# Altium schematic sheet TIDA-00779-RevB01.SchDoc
size 431 x 279 mm; Date: Not shown in title block; ApprovedBy: Not shown in title block; CheckedBy: Not shown in title block; Author: Not shown in title block; CompanyName: Not shown in title block; Engineer: Not shown in title block; Organization: Not shown in title block; Address1: Not shown in title block; Address2: Not shown in title block; Address3: Not shown in title block; Address4: Not shown in title block; DocumentNumber: 1; Revision: Use project parameter SCH_Rev; SheetNumber: 2; SheetTotal: 3; PageSetup: Record=PageOptions¦CenterHorizontal=True¦CenterVertical=True¦PrintScale=0.62¦XCorrection=1.00¦YCorrection=1.00¦PrintKind=0¦BorderSize=5000000¦LeftOffset=0¦BottomOffset=0¦Orientation=2¦PaperLength=1000¦PaperWidth=1000¦Scale=100¦PaperSource=15¦PrintQuality=600¦MediaType=1¦DitherType=10¦PaperKind=Letter¦PrintScaleMode=1
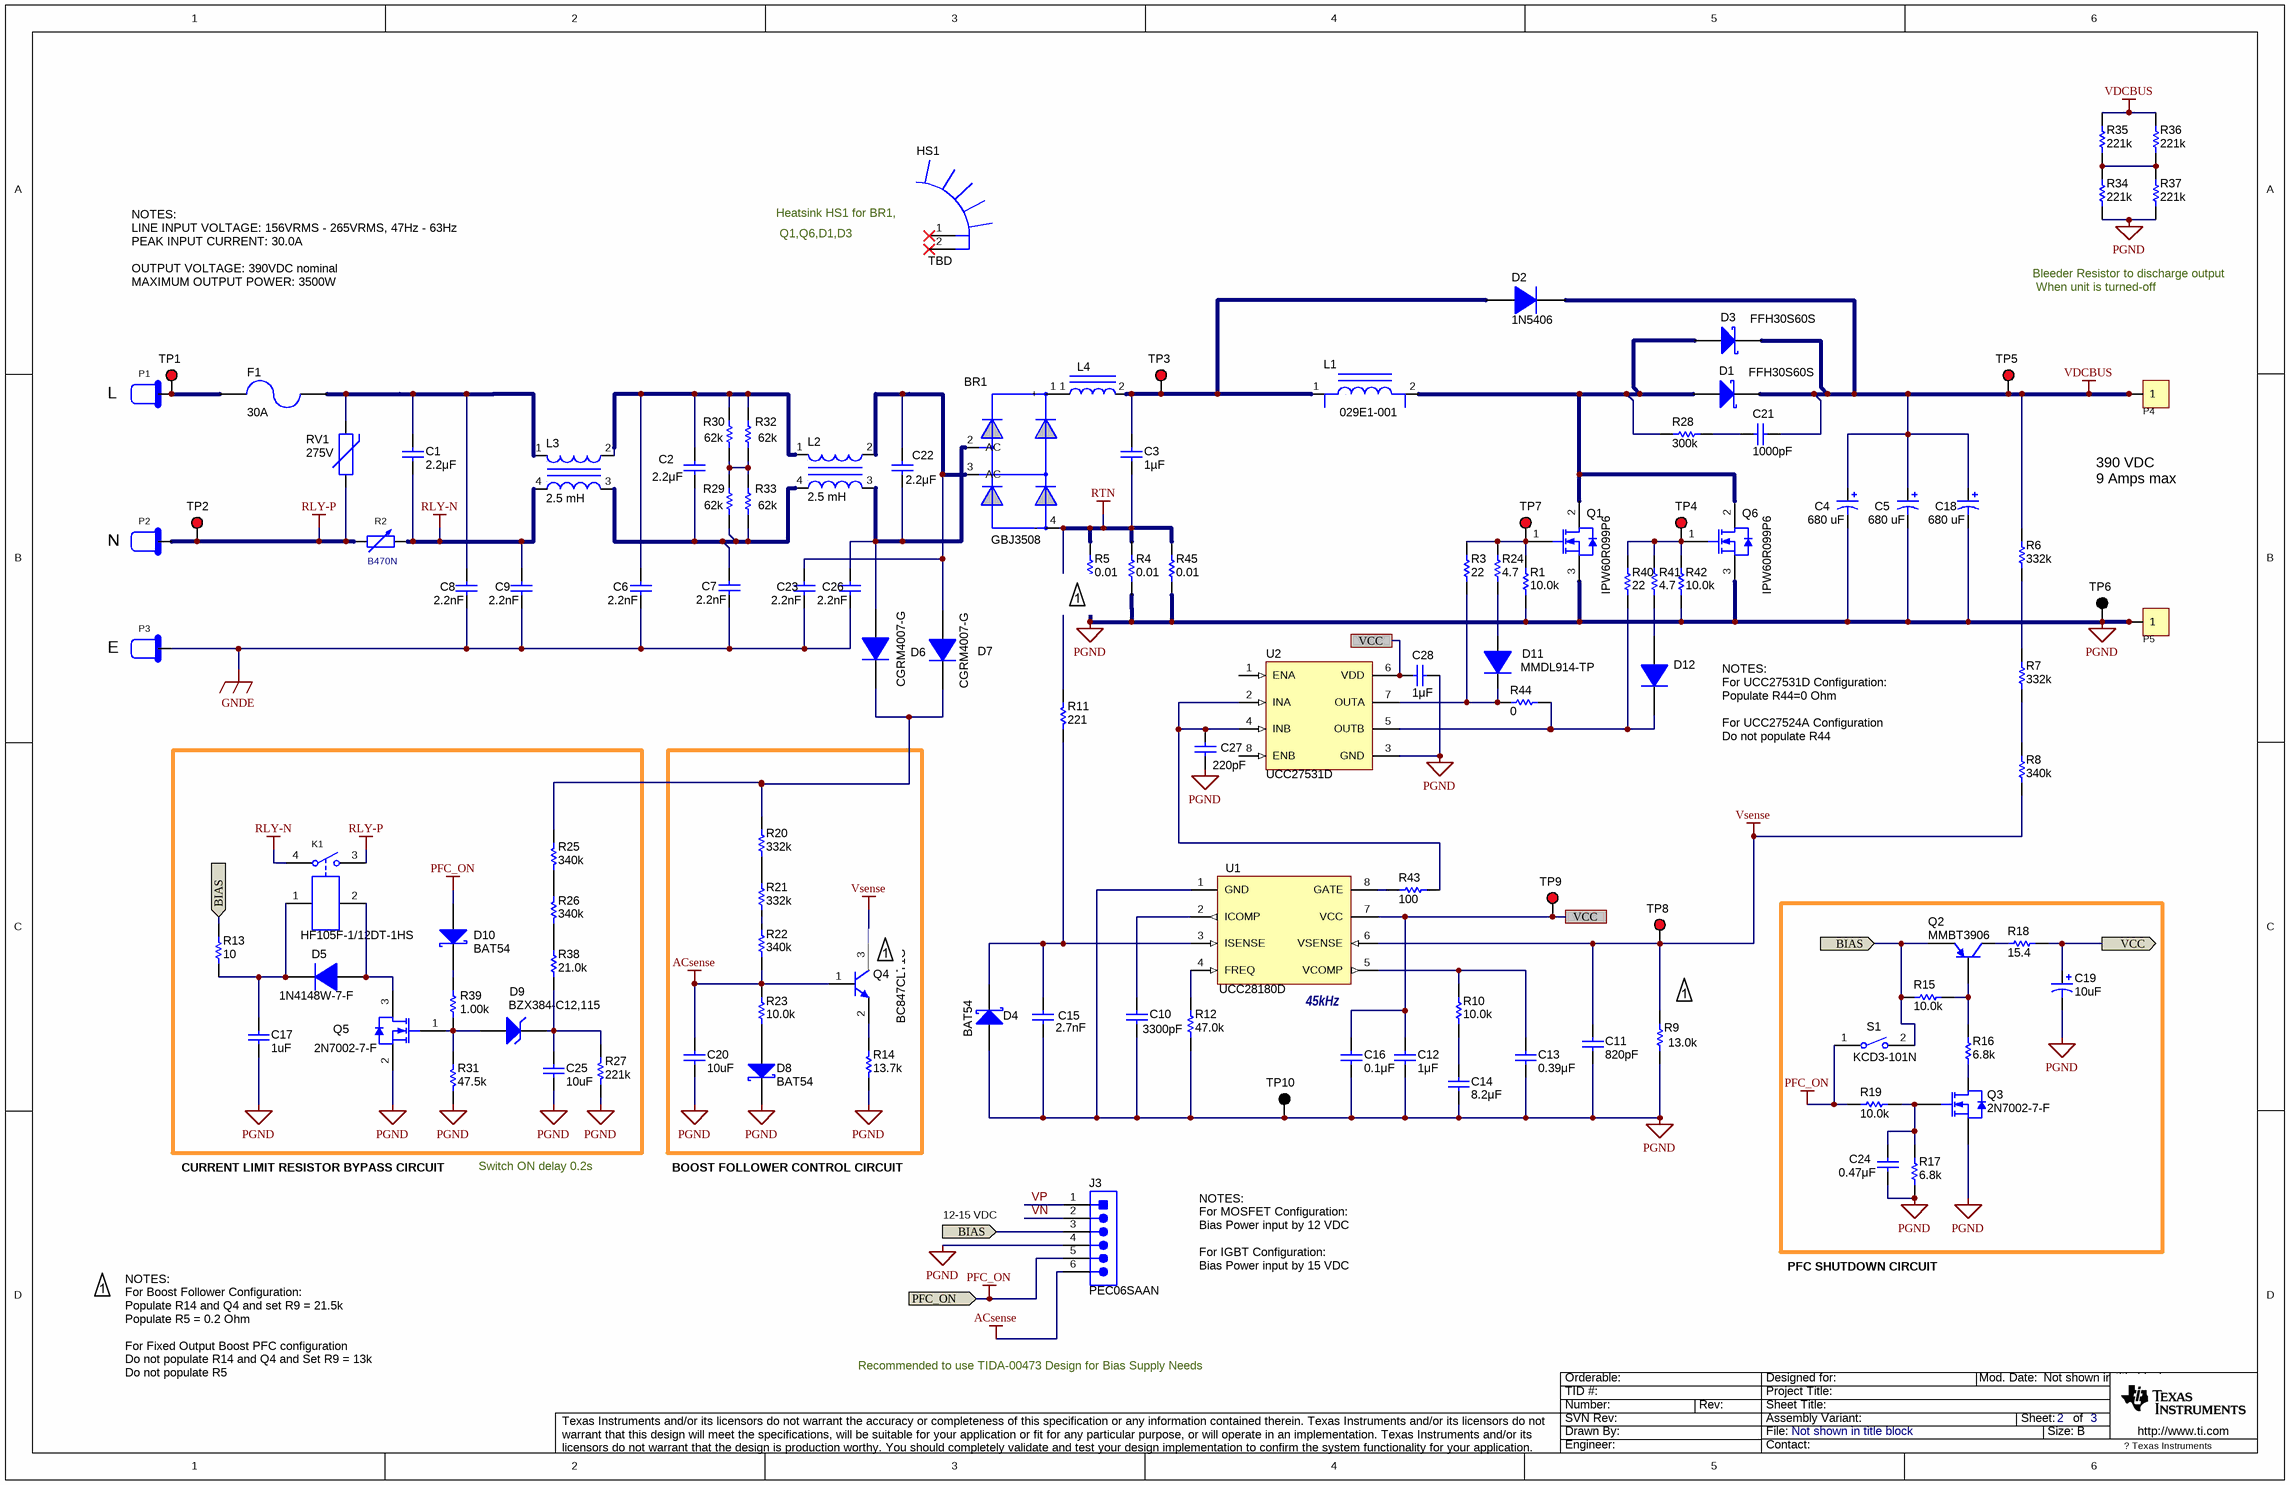
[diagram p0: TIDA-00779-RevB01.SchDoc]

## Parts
BR1  GBJ3508  [BRIDGE-GBJ1510-BV]
C1  ValueDisplayed: 2.2μF  [B32923_29.5mm]  (hidden comment: B32923C3225K)
C2  ValueDisplayed: 2.2μF  [B32923_29.5mm]  (hidden comment: B32923C3225K)
C3  ValueDisplayed: 1µF  [B32923_20.5mm]  (hidden comment: B32923C3105K)
C4  value 680 uF  [E/P10/D36/E2]  (hidden comment: LGG2W681MELC50)
C5  value 680 uF  [E/P10/D36/E2]  (hidden comment: LGG2W681MELC50)
C6  2.2nF  [C/10/12/5]
C7  2.2nF  [C/10/12/5]
C8  2.2nF  [C/10/12/5]
C9  2.2nF  [C/10/12/5]
C10  ValueDisplayed: 3300pF  [0603]  (hidden comment: GRM188R71H472KA01D)
C11  ValueDisplayed: 820pF  [0603]  (hidden comment: C0603C821K5RACTU)
C12  ValueDisplayed: 1μF  [0603_095]  (hidden comment: C0603C105K3RACTU)
C13  ValueDisplayed: 0.39μF  [0603]  (hidden comment: C0603C394K4RACTU)
C14  ValueDisplayed: 8.2μF  [0603]  (hidden comment: 0603ZD475KAT2A)
C15  ValueDisplayed: 2.7nF  [0603]  (hidden comment: 06031C272JAT2A)
C16  ValueDisplayed: 0.1μF  [0603]  (hidden comment: 0603YC104JAT2A)
C17  ValueDisplayed: 1uF  [0603]  (hidden comment: C1608X7R1E105K080AB)
C18  value 680 uF  [E/P10/D36/E2]  (hidden comment: LGG2W681MELC50)
C19  ValueDisplayed: 10uF  [PW_500x700]  (hidden comment: UPW1V100MDD6)
C20  ValueDisplayed: 10uF  [0805_HV]  (hidden comment: C2012X5R1E106K125AB)
C21  ValueDisplayed: 1000pF  [1206]  (hidden comment: 1206AC102KAT1A)
C22  ValueDisplayed: 2.2μF  [B32923_29.5mm]  (hidden comment: B32923C3225K)
C23  2.2nF  [C/10/12/5]
C24  ValueDisplayed: 0.47μF  [0603]  (hidden comment: C0603C474K4RACTU)
C25  ValueDisplayed: 10uF  [1206]  (hidden comment: UMK316BBJ106ML-T)
C26  2.2nF  [C/10/12/5]
C27  ValueDisplayed: 220pF  [0603]  (hidden comment: C1608X7R1H221K)
C28  ValueDisplayed: 1μF  [0603]  (hidden comment: UMK107AB7105KA-T)
D1  FFH30S60S  [TO247BV-D]
D2  1N5406  [DO-201AD]
D3  FFH30S60S  [TO247BV-D]
D4  Alternate PartNumber: BAT54  [sod-323]  (hidden comment: BAT54HT1G)
D5  1N4148W-7-F  [SOD-123]
D6  CGRM4007-G  [MINI-SMA]
D7  CGRM4007-G  [MINI-SMA]
D8  Alternate PartNumber: BAT54  [sod-323]  (hidden comment: BAT54HT1G)
D9  BZX384-C12,115  [sod-323]
D10  Alternate PartNumber: BAT54  [sod-323]  (hidden comment: BAT54HT1G)
D11  MMDL914-TP  [sod-323]
D12  MMDL914-TP  [sod-323]  (value not drawn)
F1  30A  [TBD]
HS1  TBD  [HS_ASS_0595]
J3  PEC06SAAN  [HDR1X6]
K1  HF105F-1/12DT-1HS  [RY-SLA-S112DM1]
L1  029E1-001  [L4p-55*50P40*45]
L2  2.5 mH  [L4p-56*42P42*38-LT38-4P]
L3  2.5 mH  [L4p-56*42P42*38-LT38-4P]
L4  (no value)
P1  L  [P-CONNECT]
P2  N  [P-CONNECT]
P3  E  [P-CONNECT]
P4  TH  [PCB-7(M4)]  (value not drawn)
P5  TH  [PCB-7(M4)]  (value not drawn)
Q1  IPW60R099P6  [TO-247BV2]
Q2  MMBT3906  [SOT-23]
Q3  2N7002-7-F  [SOT-23]
Q4  BC847CLT1G  [SOT-23]
Q5  2N7002-7-F  [SOT-23]
Q6  IPW60R099P6  [TO-247BV2]
R1  ValueDisplayed: 10.0k  [0603]  (hidden comment: CRCW060310K0FKEA)
R2  B470N  [PTC-18*13P10]
R3  ValueDisplayed: 22  [1206]  (hidden comment: CRCW120622R0JNEA)
R4  ValueDisplayed: 0.01  [R/P10/5W]
R5  ValueDisplayed: 0.01  [R/P10/5W]
R6  ValueDisplayed: 332k  [1206]  (hidden comment: CRCW1206332KFKEA)
R7  ValueDisplayed: 332k  [1206]  (hidden comment: CRCW1206332KFKEA)
R8  ValueDisplayed: 340k  [1206]  (hidden comment: CRCW1206340KFKEA)
R9  ValueDisplayed: 13.0k  [0603]  (hidden comment: CRCW060313K0FKEA)
R10  ValueDisplayed: 10.0k  [0603]  (hidden comment: CRCW060310K0FKEA)
R11  value 221  [0603M]  (hidden comment: CRCW0603221RFKEA)
R12  ValueDisplayed: 47.0k  [0603]  (hidden comment: RT0603DRE0747KL)
R13  ValueDisplayed: 10  [1206]  (hidden comment: CRCW1206100RFKEA)
R14  ValueDisplayed: 13.7k  [0603]  (hidden comment: CRCW060313K7FKEA)
R15  value 10.0k  [0603]  (hidden comment: CRCW060310K0FKEA)
R16  ValueDisplayed: 6.8k  [0603]  (hidden comment: CRCW06036K80JNEA)
R17  ValueDisplayed: 6.8k  [0603]  (hidden comment: CRCW06036K80JNEA)
R18  ValueDisplayed: 15.4  [0603]  (hidden comment: CRCW060315R4FKEA)
R19  value 10.0k  [0603]  (hidden comment: CRCW060310K0FKEA)
R20  ValueDisplayed: 332k  [1206]  (hidden comment: CRCW1206332KFKEA)
R21  ValueDisplayed: 332k  [1206]  (hidden comment: CRCW1206332KFKEA)
R22  ValueDisplayed: 340k  [1206]  (hidden comment: CRCW1206340KFKEA)
R23  ValueDisplayed: 10.0k  [0603]  (hidden comment: CRCW060310K0FKEA)
R24  ValueDisplayed: 4.7  [1206]  (hidden comment: CRCW12064R70JNEA)
R25  ValueDisplayed: 340k  [1206]  (hidden comment: CRCW1206340KFKEA)
R26  ValueDisplayed: 340k  [1206]  (hidden comment: CRCW1206340KFKEA)
R27  ValueDisplayed: 221k  [0603]  (hidden comment: CRCW0603221KFKEA)
R28  ValueDisplayed: 300k  [R5/D4.4V]  (hidden comment: CRM2512-FX-43R2ELF)
R29  ValueDisplayed: 62k  [2512]  (hidden comment: CRCW251262K0JNEG)
R30  ValueDisplayed: 62k  [2512]  (hidden comment: CRCW251262K0JNEG)
R31  ValueDisplayed: 47.5k  [0603]  (hidden comment: CRCW060347K5FKEA)
R32  ValueDisplayed: 62k  [2512]  (hidden comment: CRCW251262K0JNEG)
R33  ValueDisplayed: 62k  [2512]  (hidden comment: CRCW251262K0JNEG)
R34  ValueDisplayed: 221k  [1206]  (hidden comment: CRCW1206221KFKEA)
R35  ValueDisplayed: 221k  [1206]  (hidden comment: CRCW1206221KFKEA)
R36  ValueDisplayed: 221k  [1206]  (hidden comment: CRCW1206221KFKEA)
R37  ValueDisplayed: 221k  [1206]  (hidden comment: CRCW1206221KFKEA)
R38  ValueDisplayed: 21.0k  [1206]  (hidden comment: CRCW120621K0FKEA)
R39  ValueDisplayed: 1.00k  [0603]  (hidden comment: CRCW06031K00FKEA)
R40  ValueDisplayed: 22  [1206]  (hidden comment: CRCW120622R0JNEA)
R41  ValueDisplayed: 4.7  [1206]  (hidden comment: CRCW12064R70JNEA)
R42  ValueDisplayed: 10.0k  [0603]  (hidden comment: CRCW060310K0FKEA)
R43  ValueDisplayed: 100  [0603]  (hidden comment: RT0603DRE07100RL)
R44  ValueDisplayed: 0  [1206]  (hidden comment: RC1206JR-070RL)
R45  ValueDisplayed: 0.01  [R/P10/5W]
RV1  value 275V  [VAR_S10K275E2]  (hidden comment: S10K275E2)
S1  KCD3-101N
TP1  5000  [Keystone5000]  (value not drawn)
TP2  5000  [Keystone5000]  (value not drawn)
TP3  5000  [Keystone5000]  (value not drawn)
TP4  5000  [Keystone5000]  (value not drawn)
TP5  5000  [Keystone5000]  (value not drawn)
TP6  5001  [Keystone5001]  (value not drawn)
TP7  5000  [Keystone5000]  (value not drawn)
TP8  5000  [Keystone5000]  (value not drawn)
TP9  5000  [Keystone5000]  (value not drawn)
TP10  5001  [Keystone5001]  (value not drawn)
U1  UCC28180D  [D0008A_N]
U2  UCC27531D  [D0008A_N]

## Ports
BIAS, PFC_ON (in), VCC

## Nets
ACsense: C20.1 J3.6 Q4.1(B) R22.1 R23.1
GNDE: C6.2 C7.2 C8.2 C9.2 C23.2 C26.2 P3.1
PFC_ON: D10.2(A) J3.5 R19.1 S1.1 ; port PFC_ON
PGND: C4.2(-) C5.2(-) C10.2 C11.2 C12.2 C13.2 C14.2 C15.2 C16.2 C17.2 C18.2(-) C19.2(-) C20.2 C24.2 C25.2 C27.2 C28.1 D4.2(A) D8.1(K) J3.4 P5.1 P5.2 P5.3 P5.4 Q1.3(S) Q3.2(S) Q5.2(S) Q6.3(S) R1.2 R4.1 R5.1 R9.1 R12.1 R14.2 R17.1 R27.1 R31.1 R34.1 R37.1 R42.2 R45.1 TP6.1 TP10.1 U1.1(GND) U2.3(GND)
RLY-N: C1.2 C9.1 K1.4 L3.4 R2.2
RLY-P: K1.3 P2.1 R2.1 RV1.1 TP2.1
RTN: BR1.4(-) C3.2 R4.2 R5.2 R11.1 R45.2
VDCBUS: C4.1(+) C5.1(+) C18.1(+) C21.1 D1.1(K) D2.1(K) D3.1(K) P4.1 P4.2 P4.3 P4.4 R6.2 R35.2 R36.2 TP5.1
Vsense: C11.1 Q4.3(C) R8.1 R9.2 TP8.1 U1.6(VSENSE)
BIAS: J3.3 Q2.2(E) R13.1 R15.1 S1.2 ; port BIAS
VCC: C12.1 C16.1 C19.1(+) C28.2 R18.2 TP9.1 U1.7(VCC) U2.6(VDD) ; port VCC
VN: J3.2
VP: J3.1
NetBR1_1: BR1.1(+) L4.1
NetBR1_2: BR1.2(AC) C22.2 C26.1 D6.2(A) L2.3
NetBR1_3: BR1.3(AC) C22.1 C23.1 D7.2(A) L2.2
NetC1_1: C1.1 C8.1 F1.1 L3.1 RV1.2
NetC2_1: C2.1 C6.1 L2.1 L3.2 R30.2 R32.2
NetC2_2: C2.2 C7.1 L2.4 L3.3 R29.1 R33.1
NetC3_1: C3.1 D2.2(A) L1.1 L4.2 TP3.1
NetC10_1: C10.1 U1.2(ICOMP)
NetC13_1: C13.1 R10.1 U1.5(VCOMP)
NetC14_1: C14.1 R10.2
NetC15_1: C15.1 D4.1(K) R11.2 U1.3(ISENSE)
NetC17_1: C17.1 D5.1(K) K1.1 R13.2
NetC21_2: C21.2 R28.2
NetC24_1: C24.1 Q3.1(G) R17.2 R19.2
NetC25_1: C25.1 D9.1(K) R27.2 R38.2
NetC27_1: C27.1 R43.2 U2.2(INA) U2.4(INB)
NetD1_2: D1.2(A) D3.2(A) L1.2 Q1.2(D) Q6.2(D) R28.1
NetD5_2: D5.2(A) K1.2 Q5.3(D)
NetD6_1: D6.1(K) D7.1(K) R20.2 R25.2
NetD8_2: D8.2(A) R23.2
NetD9_2: D9.2(A) Q5.1(G) R31.2 R39.2
NetD10_1: D10.1(K) R39.1
NetD11_1: D11.1(K) R3.1 R44.1 U2.7(OUTA)
NetD11_2: D11.2(A) R24.1
NetD12_1: D12.1(K) R40.1 R44.2 U2.5(OUTB)
NetD12_2: D12.2(A) R41.1
NetF1_2: F1.2 P1.1 TP1.1
NetQ1_1: Q1.1(G) R1.1 R3.2 R24.2 TP7.1
NetQ2_1: Q2.1(B) R15.2 R16.2
NetQ2_3: Q2.3(C) R18.1
NetQ3_3: Q3.3(D) R16.1
NetQ4_2: Q4.2(E) R14.1
NetQ6_1: Q6.1(G) R40.2 R41.2 R42.1 TP4.1
NetR6_1: R6.1 R7.2
NetR7_1: R7.1 R8.2
NetR12_2: R12.2 U1.4(FREQ)
NetR20_1: R20.1 R21.1
NetR21_2: R21.2 R22.2
NetR25_1: R25.1 R26.1
NetR26_2: R26.2 R38.1
NetR29_2: R29.2 R30.1 R32.1 R33.2
NetR34_2: R34.2 R35.1 R36.1 R37.2
NetR43_1: R43.1 U1.8(GATE)

Not connected (* = marked no-connect by the designer): HS1 1* 2*; U2 1(ENA) 8(ENB)

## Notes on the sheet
- Q1,Q6,D1,D3
- Heatsink HS1 for BR1,
- NOTES:
  LINE INPUT VOLTAGE: 156VRMS - 265VRMS, 47Hz - 63Hz
  PEAK INPUT CURRENT: 30.0A
  OUTPUT VOLTAGE: 390VDC nominal
  MAXIMUM OUTPUT POWER: 3500W
- When unit is turned-off
- Bleeder Resistor to discharge output
- 390 VDC
  9 Amps max
- NOTES:
  For UCC27531D Configuration:
  Populate R44=0 Ohm
  For UCC27524A Configuration
  Do not populate R44
- (near U1) 45kHz
- CURRENT LIMIT RESISTOR BYPASS CIRCUIT
- Switch ON delay 0.2s
- BOOST FOLLOWER CONTROL CIRCUIT
- 12-15 VDC
- NOTES:
  For MOSFET Configuration:
  Bias Power input by 12 VDC
  For IGBT Configuration:
  Bias Power input by 15 VDC
- PFC SHUTDOWN CIRCUIT
- NOTES:
  For Boost Follower Configuration:
  Populate R14 and Q4 and set R9 = 21.5k
  Populate R5 = 0.2 Ohm
  For Fixed Output Boost PFC configuration
  Do not populate R14 and Q4 and Set R9 = 13k
  Do not populate R5
- Recommended to use TIDA-00473 Design for Bias Supply Needs

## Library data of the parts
BR1 = D-BRIDGE_GBJ_15A_SERIES: Diode, Bridge Rectifier, GPP 35A 800V GBJ; Manufacturer: Micro Commercial Co; Area: 25452
C1 C2 C22 = B32923C3225K: CAP, Film, 2.2 μF, 630 V, +/- 10%, TH; Manufacturer: TDK; Polarized: N; CompType: Capacitor; Value: 2.2uF; U/M: EA; Cap_F: 0.0000022; Tolerance_%: 10; Value1: Unknown; VDC_V: 630; Value2: 630V; TaMax_C: 110
C3 = B32923C3105K: CAP, Film, 1 µF, 630 V, +/- 10%, 0.018 ohm, TH; Manufacturer: TDK; Polarized: N; CompType: Capacitor; Value: 1uF; U/M: EA; Cap_F: 0.000001; Tolerance_%: 10; VDC_V: 630; Value2: 630V; ESR_ohm: 0.018; IRMS_A: 0.097; TaMax_C: 110; AEC Category: Q200
C4 C5 C18 = 450QXW220MEFC18X50: CAP, ALUMINIUM, RADIAL, 680 uF, 450 V, 20%, TH; Manufacturer: RUBYCON; CompType: Aluminium Capacitor; SymbolCreator: x0199378
C6-C9 C23 C26 = CS11-E2GA222MYNS: CAP CER 2200PF 400VAC 20% RADIAL DISC 10mm Dia; PartNumber: CD90ZU2GA222MYNKA; Manufacturer: TDK; Polarized: N; CompType: Capacitor; U/M: EA; Cap_F: 0.0000000010; Tolerance_%: 20; Value1: Unknown; VDC_V: 300; Value2: 400V; TempCo: E; TaMin_C: -25; TaMax_C: 222; Cap_Case: Disc, 10.5x7mm
C10 = GRM188R71H472KA01D: CAP, CERM, 3300 pF, 50 V, +/- 10%, X7R, 0603; Manufacturer: MuRata; Polarized: N; CompType: Capacitor; Value: 4700pF; U/M: EA; Cap_F: 0.0000000047; Tolerance_%: 10; Value1: Unknown; VDC_V: 50; Value2: 50V; TaMin_C: -55; TaMax_C: 125
C11 = C0603C821K5RACTU: CAP, CERM, 820 pF, 50 V, +/- 10%, X7R, 0603; Manufacturer: Kemet; Value: 820pF; Polarized: N; CompType: Capacitor; U/M: EA; Cap_F: 0.00000000082; Tolerance_%: 10; Value1: Unknown; VDC_V: 50; Value2: 50V; TaMin_C: -55; TaMax_C: 125
C12 = C0603C105K3RACTU: CAP, CERM, 1 μF, 25 V, +/- 10%, X7R, 0603_095; Manufacturer: Kemet; Polarized: N; CompType: Capacitor; Value: 1uF; U/M: EA; Cap_F: 0.000001; Tolerance_%: 10; Value1: Unknown; VDC_V: 25; Value2: 25V; TaMin_C: -55; TaMax_C: 125; Cap_Case: 0603
C13 = C0603C394K4RACTU: CAP, CERM, 0.39 μF, 16 V, +/- 10%, X7R, 0603; Manufacturer: Kemet; Polarized: N; CompType: Capacitor; Value: 0.39uF; U/M: EA; Cap_F: 0.00000039; Tolerance_%: 10; Value1: Unknown; VDC_V: 16; Value2: 16V; TaMin_C: -55; TaMax_C: 125
C14 = 0603ZD475KAT2A: CAP, CERM, 8.2 μF, 25 V, +/- 10%, X5R, 0603; Manufacturer: AVX; Polarized: N; CompType: Capacitor; Value: 4.7uF; U/M: EA; Cap_F: 0.0000047; Tolerance_%: 10; Value1: Unknown; Value2: 10V; TaMin_C: -55; TaMax_C: 85
C15 = 06031C272JAT2A: CAP, CERM, 2700 pF, 100 V, +/- 5%, X7R, 0603; Manufacturer: AVX; Value: 2700pF; Polarized: N; CompType: Capacitor; U/M: EA; Cap_F: 0.0000000027; Tolerance_%: 5; ESR_ohm: 0.174; Value1: 0.174 ohm; VDC_V: 100; Value2: 100V; TaMin_C: -55; TaMax_C: 125
C16 = 0603YC104JAT2A: CAP, CERM, 0.1 μF, 16 V, +/- 5%, X7R, 0603; Manufacturer: AVX; Polarized: N; CompType: Capacitor; Value: 0.1uF; U/M: EA; Cap_F: 0.0000001; Tolerance_%: 5; ESR_ohm: 0.039; Value1: 0.039 ohm; VDC_V: 16; Value2: 16V; TaMin_C: -55; TaMax_C: 125
C17 = C1608X7R1E105K080AB: CAP, CERM, 1u, 25 V, +/- 10%, X7R, 0603; Manufacturer: TDK; Polarized: N; CompType: Capacitor; Value: 1uF; U/M: EA; Cap_F: 0.000001; Tolerance_%: 10; Value1: Unknown; VDC_V: 25; Value2: 25V; TaMin_C: -55; TaMax_C: 125
C19 = UPW1V100MDD6: CAP, AL, 10uF, 35V, +/-20%, 0.95 ohm, TH; Manufacturer: Nichicon; Polarized: Y; CompType: Capacitor; U/M: EA; Cap_F: 0.00001; Tolerance_%: 20; VDC_V: 35; ESR_Ohm: 0.95; IRMS_A: 0.12; TaMin_C: -55; TaMax_C: 105; Cap_Case: 5x7
C20 = C2012X5R1E106K125AB: CAP, CERM, 10uF, 25 V, +/- 10%, X5R, 0805; Manufacturer: TDK; Polarized: N; CompType: Capacitor; U/M: EA; Cap_F: 0.00001; Tolerance_%: 10; Value1: Unknown; VDC_V: 25; Value2: 25V; TaMin_C: -55; TaMax_C: 85; Cap_Case: 0805
C21 = GRM31A7U3A331JW31D: CAP, CERM, 1000 pF, 1000 V, +/- 5%, X7R, 1206; Manufacturer: AVX; Polarized: N; CompType: Capacitor; Value: 1000pF; U/M: EA; Cap_F: 0.00000000033; Tolerance_%: 5; Value1: Unknown; VDC_V: 1000; Value2: 1000V; TempCo: U2J; TaMin_C: -55; TaMax_C: 125
C24 = C0603C474K4RACTU: CAP, CERM, 0.47 μF, 16 V, +/- 10%, X7R, 0603; Manufacturer: Kemet; Polarized: N; CompType: Capacitor; Value: 0.47uF; U/M: EA; Cap_F: 0.00000047; Tolerance_%: 10; Value1: Unknown; VDC_V: 16; Value2: 16V; TaMin_C: -55; TaMax_C: 125
C25 = GRM319R61H475KA12: CAP CER 10UF 50V 20% X5R 1206; Manufacturer: Taiyo Yuden; Polarized: N; CompType: Capacitor; U/M: EA; Cap_F: 0.0000010; Tolerance_%: 20; Value1: Unknown; VDC_V: 50; TaMin_C: -55; TaMax_C: 85
C27 = C1608X7R1H221K: CAP, CERM, 220 pF, 50 V, +/- 10%, X7R, 0603; Manufacturer: TDK; Polarized: N; CompType: Capacitor; Value: 220pF; U/M: EA; Cap_F: 0.00000000022; Tolerance_%: 10; Value1: Unknown; VDC_V: 50; Value2: 50V; TaMin_C: -55; TaMax_C: 125
C28 = UMK107AB7105KA-T: CAP, CERM, 1 μF, 50 V, +/- 10%, X7R, 0603; Manufacturer: Taiyo Yuden; Polarized: N; CompType: Capacitor; Value: 1uF; U/M: EA; Cap_F: 0.000001; Tolerance_%: 10; Value1: Unknown; VDC_V: 50; Value2: 50V; TaMin_C: -55; TaMax_C: 125
D1 D3 = C3D04060A: Diode, 600 V, 30 A, TH; Manufacturer: Cree; Value: 600V; U/M: EA; Vf_V: 1.8; Value1: 4A; Value2: 1.8V; Io_A: 4; Vr_V: 600; TJmax_C: 175; RJC_CperW: 11.5
D2 = 1N5406: Diode, Switching-Bridge, 600 V, 3 A, TH; Manufacturer: Vishay-Semiconductor; U/M: EA; Vf_V: 1.2; Value: 600V; Value1: 3A; Value2: 1.2V; Io_A: 3; Vr_V: 600; TJmax_C: 150
D4 D8 D10 = BAT54HT1G: Diode, Schottky, 30V, 0.2A, SOD-323; Manufacturer: Fairchild; U/M: EA; Vf_V: 0.35; Value2: 0.35V; Io_A: 0.2; Vr_V: 30
D5 = 1N4148W-7-F: Diode, Ultrafast, 100V, 0.15A, SOD-123; Manufacturer: Diodes Inc.; U/M: EA; Vf_V: 1.25; Value2: 1.25V; Io_A: 0.15; Vr_V: 100; TJmax_C: 150
D6 D7 = CGRM4007-G: Diode, P-N, 1000 V, 1 A, 3.9x1.7x1.8mm; Manufacturer: Comchip Technology; U/M: EA; Vf_V: 1.1; Value: 1000V; Value1: 1A; Value2: 1.1V; Io_A: 1; Vr_V: 1000; TJmax_C: 150
D9 = BZX384-C12,115: Diode, Zener, 12V, 300mW, SOD-323; Manufacturer: NXP Semiconductor; SymbolCreator: a0412235; U/M: EA; Power_W: 0.3; Vz_V: 12; Value1: 0.3W; RJA_CperW: 415
D11 D12 = MMDL914-TP: Diode, Switching, 100 V, 0.2 A, SOD-323; Manufacturer: Micro Commercial Components; Value: 100V; U/M: EA; Vf_V: 1; Value1: 0.2A; Value2: 1V; Io_A: 0.2; Vr_V: 100; TJmax_C: 150; RJC_CperW: 635
F1 = Fuse: FUSE CLIP, CARTRIDGE, 250V, 30A, PCB; Manufacturer: Used in BOM report; U/M: EA
HS1 = 531002B02500G: HEATSINK ALUM Black Anodized, Board Mount; Manufacturer: Assmann; SymbolCreator: a0799628
J3 = PEC06SAAN: Header, 100mil, 6x1, Tin, TH; Manufacturer: Sullins Connector Solutions; SymbolCreator: a0412235; U/M: EA
K1 = Relay-SPST: Single-Pole, 240VAC, 30A
L1 = 750342810: INDUCTOR, 170 uH, 30A, 10%, TH; Manufacturer: Yun Lu; SymbolCreator: x0199378; Value: 780uH
L2 L3 = 8113-RC: INDUCTOR, CHOKE, COMMON MODE, 2.5 mH, 30 A, 22 mOHM, TH; Manufacturer: Bourns Inc; SymbolCreator: x0199378
L4 = IND_74451147: Inductor, 0.5A, 0.160 Ohm; Manufacturer: Wurth Elektronik; Area: 43.68 mm; Value: 47 uH
P1-P3 = CON1: Pad
P4 P5 = 63824-1: Text Field2: 6.3mm*0.8mm; Text Field3: 1; Text Field4: 常规件
Q1 Q6 = IPP60R190P6: MOSFET, N-CH, 600 V, 37.9 A, TO-247; Manufacturer: Infineon Technologies; Value: 600 V; SymbolCreator: x0199378
Q2 = MMBT3906, Fairchild Semiconductor: Transistor, PNP, 40V, 0.2A, SOT-23; CompType: BJT; PNP: 1; NPN: 0; Vceo_V: 40; Vcesat1_V: 0.25; Value: 0.25V; IcRated_A: 0.2; HfeMax: 300; TaMin_C: -55; TaMax_C: 150; U/M: EA
Q3 Q5 = 2N7002-7-F: MOSFET, N-CH, 60V, 0.17A, SOT-23; Manufacturer: Diodes Inc.; Alternate Manufacturer: None; U/M: EA; ChType: N; VdsMax_V: 60; Value1: 7.5 ohm; Rdson45_Ohm: 7.5; Value2: 223 nC; QgTyp_nC: 223; Vgs_V: 20; IdsMax_A: 0.17
Q4 = BC847CLT1G, ON Semiconductor: Transistor, NPN, 45 V, 0.1 A, SOT-23; CompType: BJT; PNP: 0; NPN: 1; Vceo_V: 45; Vcesat1_V: 0.7; Value: 45 V; IcRated_A: 0.1; Value1: 0.1 A; HfeMax: 800; TaMin_C: -55; TaMax_C: 150; U/M: EA
R1 R10 R23 R42 = CRCW060310K0FKEA: RES, 10.0 k, 1%, 0.1 W, 0603; Manufacturer: Vishay-Dale; CompType: Resistor; Value: 10.0k; Res_ohm: 10000; Value_Code: 10k0; Tolerance_%: 1; Power_W: 0.1; Value2: 0.1W; VDC_V: 75; TempCo: 100 ppm/C; EIA_Code: E96; U/M: EA
R2 = Res Adj2: PTC, 47 ohm; Value: 1K; Set Position: 0.5
R3 R40 = CRCW120622R0JNEA: RES, 22, 5%, 0.25 W, 1206; Manufacturer: Vishay-Dale; CompType: Resistor; Value: 22; Value_Code: 22R0; Tolerance_%: 5; Power_W: 0.25; Value2: 0.25W; VDC_V: 200; TempCo: 200 ppm/C; EIA_Code: E24; U/M: EA
R4 R5 R45 = CSRN2512FKR200: RES, 0.01, 1%, 5 W, TH; Manufacturer: Bourns; Value: 0.2; CompType: Resistor; Value_Code: R200; Tolerance_%: 1; Power_W: 2; Value2: 5W; TempCo: 200 ppm/C; EIA_Code: E96; U/M: EA
R6 R7 R20 R21 = CRCW1206332KFKEA: RES, 332 k, 1%, 0.25 W, 1206; Manufacturer: Vishay-Dale; Value: 332k; CompType: Resistor; Res_ohm: 332000; Tolerance_%: 1; Power_W: 0.25; Value2: 0.25W; VDC_V: 200; TempCo: 100 ppm/C; EIA_Code: E96; U/M: EA
R8 R22 R25 R26 = CRCW1206340KFKEA: RES, 340 k, 1%, 0.25 W, 1206; Manufacturer: Vishay-Dale; Value: 340k; CompType: Resistor; Res_ohm: 340000; Tolerance_%: 1; Power_W: 0.25; Value2: 0.25W; VDC_V: 200; TempCo: 100 ppm/C; EIA_Code: E96; U/M: EA
R9 = CRCW060313K0FKEA: RES, 13.0 k, 1%, 0.1 W, 0603; Manufacturer: Vishay-Dale; Value: 13.0k; CompType: Resistor; Res_ohm: 13000; Value_Code: 13k0; Tolerance_%: 1; Power_W: 0.1; Value2: 0.1W; VDC_V: 75; TempCo: 100 ppm/C; EIA_Code: E96; U/M: EA
R11 = CRCW0603221RFKEA: RES, 221 ohm, 1%, 0.1W, 0603; Manufacturer: Vishay-Dale; CompType: Resistor; Value_Code: 221R; Tolerance_%: 1; Power_W: 0.1; VDC_V: 75; TempCo: 100 ppm/C; EIA_Code: E96; U/M: EA
R12 = RT0603DRE0747KL: RES, 47.0 k, 0.5%, 0.1 W, 0603; Manufacturer: Yageo America; CompType: Resistor; Value: 47.0k; Res_ohm: 47000; Value_Code: 47k0; Tolerance_%: 0.5; Power_W: 0.1; Value2: 0.1W; VDC_V: 75; TempCo: 50 ppm/C; EIA_Code: E192; U/M: EA
R13 = CRCW1206100RFKEA: RES, 10, 1%, 0.25 W, 1206; Manufacturer: Vishay-Dale; Value: 100; CompType: Resistor; Value_Code: 100R; Tolerance_%: 1; Power_W: 0.25; Value2: 0.25W; VDC_V: 200; TempCo: 100 ppm/C; EIA_Code: E96; U/M: EA
R14 = CRCW060313K7FKEA: RES, 13.7 k, 1%, 0.1 W, 0603; Manufacturer: Vishay-Dale; Value: 13.7k; CompType: Resistor; Res_ohm: 13700; Value_Code: 13k7; Tolerance_%: 1; Power_W: 0.1; Value2: 0.1W; VDC_V: 75; TempCo: 100 ppm/C; EIA_Code: E96; U/M: EA
R15 R19 = CRCW060310K0FKEA: RES, 10.0k ohm, 1%, 0.1W, 0603; Manufacturer: Vishay-Dale; CompType: Resistor; Res_ohm: 10000; Value_Code: 10k0; Tolerance_%: 1; Power_W: 0.1; VDC_V: 75; TempCo: 100 ppm/C; EIA_Code: E96; U/M: EA
R16 R17 = CRCW06036K80JNEA: RES, 6.8 k, 5%, 0.1 W, 0603; Manufacturer: Vishay-Dale; CompType: Resistor; Value: 6.8k; Res_ohm: 6800; Value_Code: 6k80; Tolerance_%: 5; Power_W: 0.1; Value2: 0.1W; VDC_V: 75; TempCo: 200 ppm/C; EIA_Code: E24; U/M: EA
R18 = CRCW060315R4FKEA: RES, 15.4, 1%, 0.1 W, 0603; Manufacturer: Vishay-Dale; CompType: Resistor; Value: 15.4; Value_Code: 15R4; Tolerance_%: 1; Power_W: 0.1; Value2: 0.1W; VDC_V: 75; TempCo: 100 ppm/C; EIA_Code: E96; U/M: EA
R24 R41 = CRCW12064R70JNEA: RES, 4.7, 5%, 0.25 W, 1206; Manufacturer: Vishay-Dale; CompType: Resistor; Value: 4.7; Value_Code: 4R70; Tolerance_%: 5; Power_W: 0.25; Value2: 0.25W; VDC_V: 200; TempCo: 200 ppm/C; EIA_Code: E24; U/M: EA
R27 = CRCW0603221KFKEA: RES, 221 k, 1%, 0.1 W, 0603; Manufacturer: Vishay-Dale; CompType: Resistor; Value: 221k; Res_ohm: 221000; Tolerance_%: 1; Power_W: 0.1; Value2: 0.1W; VDC_V: 75; TempCo: 100 ppm/C; EIA_Code: E96; U/M: EA
R28 = CRCW2512100RFKEG: RES, 300K, 1%, 1 W, TH; Manufacturer: Vishay-Dale; CompType: Resistor; Value: 100; Tolerance_%: 1; Value2: 2W; VDC_V: 500; TempCo: 100 ppm/C; EIA_Code: E96; U/M: EA
R29 R30 R32 R33 = CRCW251262K0JNEG: RES, 62 k, 5%, 1 W, 2512; Manufacturer: Vishay-Dale; CompType: Resistor; Value: 62k; Res_ohm: 62000; Value_Code: 62k0; Tolerance_%: 5; Power_W: 1; Value2: 1W; VDC_V: 500; TempCo: 200 ppm/C; EIA_Code: E24; U/M: EA
R31 = CRCW060347K5FKEA: RES, 47.5 k, 1%, 0.1 W, 0603; Manufacturer: Vishay-Dale; CompType: Resistor; Value: 47.5k; Res_ohm: 47500; Value_Code: 47k5; Tolerance_%: 1; Power_W: 0.1; Value2: 0.1W; VDC_V: 75; TempCo: 100 ppm/C; EIA_Code: E96; U/M: EA
R34-R37 = CRCW1206221KFKEA: RES, 221 k, 1%, 0.25 W, 1206; Manufacturer: Vishay-Dale; Value: 221k; CompType: Resistor; Res_ohm: 221000; Tolerance_%: 1; Power_W: 0.25; Value2: 0.25W; VDC_V: 200; TempCo: 100 ppm/C; EIA_Code: E96; U/M: EA
R38 = CRCW120621K0FKEA: RES, 21.0 k, 1%, 0.25 W, 1206; Manufacturer: Vishay-Dale; Value: 21.0k; CompType: Resistor; Res_ohm: 21000; Value_Code: 21k0; Tolerance_%: 1; Power_W: 0.25; Value2: 0.25W; VDC_V: 200; TempCo: 100 ppm/C; EIA_Code: E96; U/M: EA
R39 = CRCW06031K00FKEA: RES, 1.00 k, 1%, 0.1 W, 0603; Manufacturer: Vishay-Dale; CompType: Resistor; Value: 1.00k; Res_ohm: 1000; Value_Code: 1k00; Tolerance_%: 1; Power_W: 0.1; Value2: 0.1W; VDC_V: 75; TempCo: 100 ppm/C; EIA_Code: E96; U/M: EA
R43 = RT0603DRE07100RL: RES, 100, 0.5%, 0.1 W, 0603; Manufacturer: Yageo America; CompType: Resistor; Value: 100; Value_Code: 100R; Tolerance_%: 0.5; Power_W: 0.1; Value2: 0.1W; VDC_V: 75; TempCo: 50 ppm/C; EIA_Code: E192; U/M: EA
R44 = RC1206JR-070RL: RES, 0, 5%, 0.25 W, 1206; Manufacturer: Yageo America; CompType: Resistor; Value: 0; Value_Code: 0000; Tolerance_%: 5; Power_W: 0.25; Value2: 0.25W; VDC_V: 200; TempCo: 200 ppm/C; EIA_Code: E24; U/M: EA
RV1 = S10K275E2: Varistor 275V RMS 10MM Radial, TH; Manufacturer: EPCOS Inc; SymbolCreator: a0412235
S1 = CHS-01TB: Switch, Slide, SPST, Top Slide; Manufacturer: Copal Electronics; SymbolCreator: a0799628; VDC_V: 6; SwitchFunction: Off-On; PositionCount: 1; CurrentRating_mA: 100
TP1-TP5 TP7-TP9 = 5000: Test Point, Miniature, Red, TH; Manufacturer: Keystone; CompType: Test Point Loop; U/M: EA
TP6 TP10 = 5001: Test Point, Miniature, Black, TH; Manufacturer: Keystone; CompType: Test Point Loop; U/M: EA
U1 = UCC28180D: 8-PIN CONTINUOUS CONDUCTION MODE (CCM) PFC CONTROLLER, D0008A; Alternate Manufacturer: None; Manufacturer: Texas Instruments; SymbolCreator: a0411947; CompType: IC; U/M: EA
U2 = UCC27524AD: Dual 5-A High-Speed Low-Side Gate Driver, D0008A; Manufacturer: Texas Instruments; SymbolCreator: a0411947; CompType: IC; U/M: EA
